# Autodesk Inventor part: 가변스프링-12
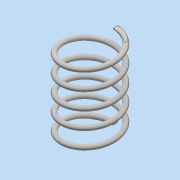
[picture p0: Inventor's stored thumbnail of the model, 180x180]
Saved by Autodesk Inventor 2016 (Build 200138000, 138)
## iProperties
Created: 2015-11
Part Number: 가변스프링-12
Material: 일반
Document SubType Name: Modeling
Designer: Administrator
Density: 1 g/cm^3
Appearance: 기본값
Mass: 1.07424 g
Surface Area: 21.7235 cm^2
Volume: 1.07424 cm^3
Author: Administrator
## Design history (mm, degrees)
sketch "스케치2"
  geometry: L1 (0, 0)-(11, 0); L2 (11, 0)-(11, 36.561); L3 (11, 36.561)-(0, 36.561); L4 (0, 36.561)-(0, 0); C1 r 1 at (11, 0)
  constraints: 8 end point, 2 parallel, 1 centre point, 1 coincident, 1 horizontal, 1 perpendicular
  dimensions: "d0" = 2 diameter of C1; "d1" = 22 diameter of L2 L4; "d2" = 36.5612 distance between parallel lines of L3 L1 (derived)
feature "코일1" sketch "스케치2" pitch "d3" = 10; turns "d5" = 5; dims "d4" = 36.5612 (= d2), "d6" = 0, angle "d7" = 90 deg, angle "d8" = 90 deg, "d9" = 0, "d10" = 0
sketch "스케치3"
  geometry: L1 (0, 12)-(0, 10) reference; 1 further point
  constraints: 1 vertical alignment
extrude "돌출1" cut sketch "스케치3" distance "d11" = 10; taper "d12" = 0 deg
node "작업 평면1"
sketch "스케치4"
  geometry: L1 (0, -1)-(0, 1) reference; 1 further point
  constraints: 1 vertical alignment
extrude "돌출2" cut sketch "스케치4" distance "d13" = 10; taper "d14" = 0 deg
node "솔리드1"
node "절단 모서리 투영1"
node "절단 모서리 투영2"
